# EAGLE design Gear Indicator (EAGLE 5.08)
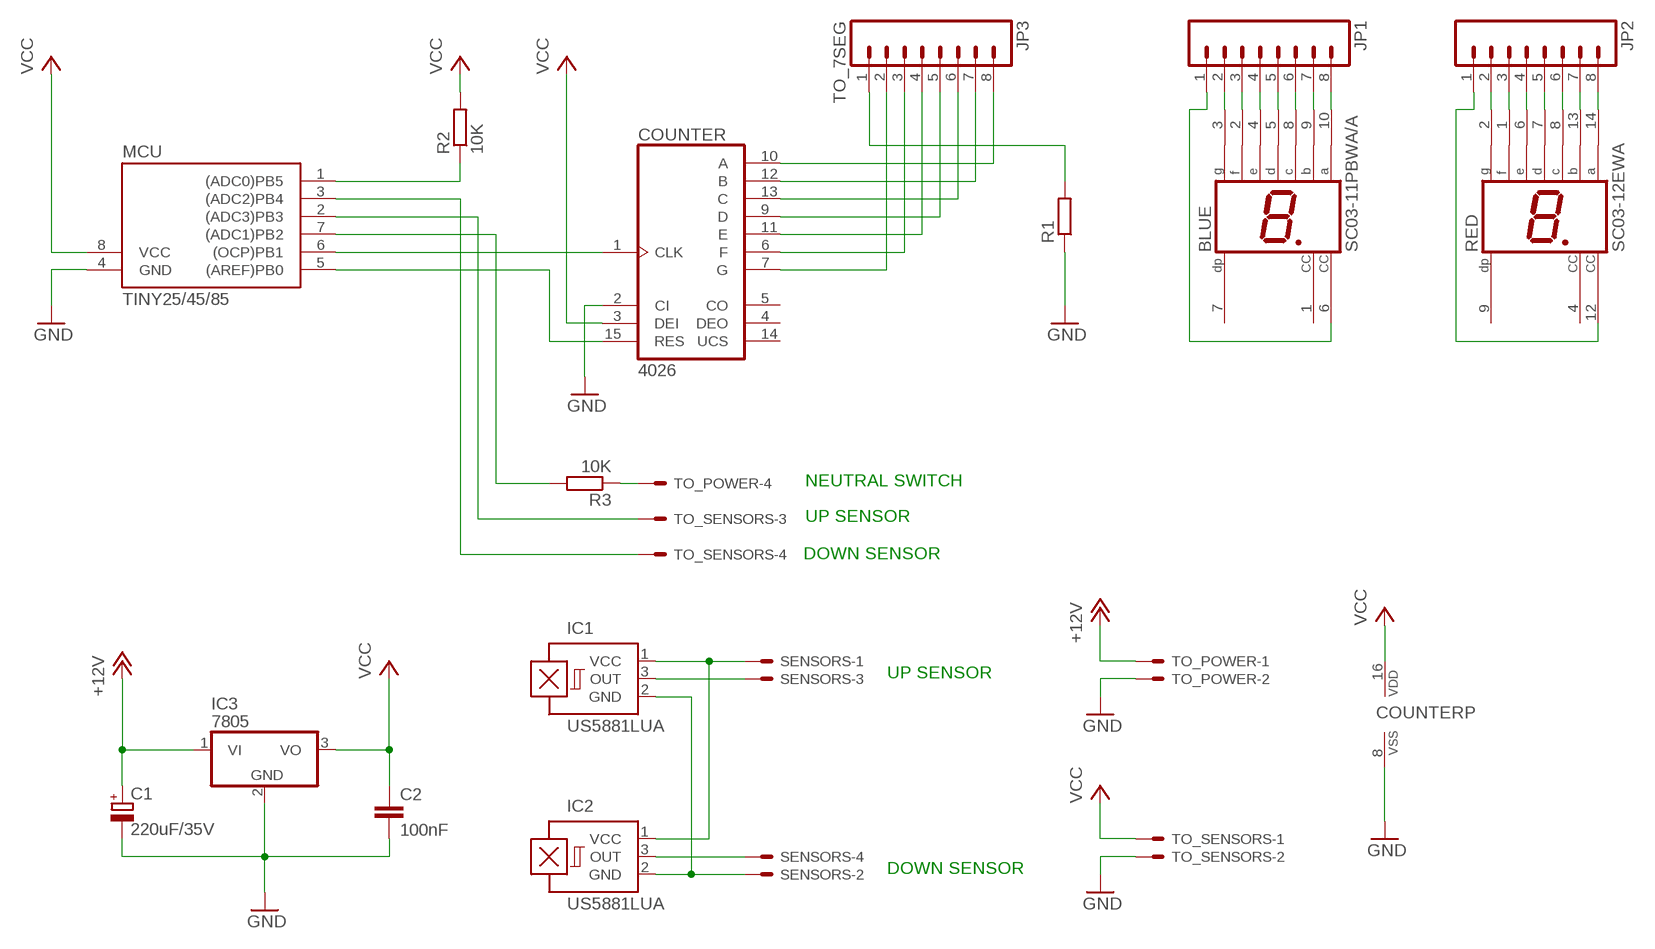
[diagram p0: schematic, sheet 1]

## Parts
BLUE  SC03-11PBWA/A  [0.3A]
C1  220uF/35V  CPOL-EUE2.5-6  [E2,5-6]
C2  100nF  C-EU050-030X075  [C050-030X075]
COUNTER  4026  4026TS  [TSSOP16]
IC1  US5881LUA  A1202UA  [SIP3-UA]
IC2  US5881LUA  A1202UA  [SIP3-UA]
IC3  7805  7805TV  [TO220V]
JP1  M08  [1X08]
JP2  M08  [1X08]
JP3  TO_7SEG  M08  [1X08]
MCU  TINY25/45/85  TINY25/45/85-20SU  [SOIC8]
R1  R-EU_0309/12  [0309/12]
R2  10K  R-EU_0207/10  [0207/10]
R3  10K  R-EU_0207/10  [0207/10]
RED  SC03-12EWA  [0.3B]
SENSORS  22-05-7048-04  [7395-04]
TO_POWER  22-05-7048-04  [7395-04]
TO_SENSORS  22-05-7048-04  [7395-04]

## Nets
+12V: C1.+ IC3.1(VI) TO_POWER.1
A: COUNTER.10(A) JP3.8
B: COUNTER.12(B) JP3.7
BLUE_A: BLUE.10(A) JP1.8
BLUE_B: BLUE.9(B) JP1.7
BLUE_C: BLUE.8(C) JP1.6
BLUE_CC: BLUE.6(CC) JP1.1
BLUE_D: BLUE.5(D) JP1.5
BLUE_E: BLUE.4(E) JP1.4
BLUE_F: BLUE.2(F) JP1.3
BLUE_G: BLUE.3(G) JP1.2
C: COUNTER.13(C) JP3.6
CC: JP3.1 R1.2
CLK: COUNTER.1(CLK) MCU.6((OCP)PB1)
D: COUNTER.9(D) JP3.5
DOWN: MCU.3((ADC2)PB4) TO_SENSORS.4
E: COUNTER.11(E) JP3.4
F: COUNTER.6(F) JP3.3
G: COUNTER.7(G) JP3.2
GND: C1.- C2.2 COUNTER.2(CI) COUNTER.8(VSS) IC3.2(GND) MCU.4(GND) R1.1 TO_POWER.2 TO_SENSORS.2
N$31: R3.1 TO_POWER.4
N$32: IC1.2(GND) IC2.2(GND) SENSORS.2
N$36: IC1.1(VCC) IC2.1(VCC) SENSORS.1
N$38: IC1.3(OUT) SENSORS.3
N$40: IC2.3(OUT) SENSORS.4
NEUTRAL: MCU.7((ADC1)PB2) R3.2
RED_A: JP2.8 RED.14(A)
RED_B: JP2.7 RED.13(B)
RED_C: JP2.6 RED.8(C)
RED_CC: JP2.1 RED.12(CC)
RED_D: JP2.5 RED.7(D)
RED_E: JP2.4 RED.6(E)
RED_F: JP2.3 RED.1(F)
RED_G: JP2.2 RED.2(G)
RESET: MCU.1((ADC0)PB5) R2.1
UP: MCU.2((ADC3)PB3) TO_SENSORS.3
VCC: C2.1 COUNTER.3(DEI) COUNTER.16(VDD) IC3.3(VO) MCU.8(VCC) R2.2 TO_SENSORS.1
ZERO: COUNTER.15(RES) MCU.5((AREF)PB0)
Unconnected: BLUE.1(CC) BLUE.7(DP) COUNTER.4(DEO) COUNTER.5(CO) COUNTER.14(UCS) RED.4(CC) RED.9(DP) TO_POWER.3

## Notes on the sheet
- NEUTRAL SWITCH
- UP SENSOR
- DOWN SENSOR
- UP SENSOR
- DOWN SENSOR

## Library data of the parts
BLUE = #vp-knightbright-0.3:SC03-11PBWA/A: LED DISPLAY 0.3'' 1-character 7-segment
C1 = rcl:CPOL-EU: POLARIZED CAPACITOR, European symbol
C2 = rcl:C-EU: CAPACITOR, European symbol
COUNTER = #vp-40xx:4026: Decade COUNTER/DIVIDER, 7-seg. outputs
IC1 IC2 = allegro:A12*?: Hall-effect bipolar switch Source: http://www.allegromicro.com/en/Products/Part_Numbers/1202/1202.pdf
IC3 = linear:78*: Positive VOLTAGE REGULATOR Source: http://cache.national.com/ds/LM/LM78L05.pdf http://www.fairchildsemi.com/ds/LM/LM7805.pdf
JP1-JP3 = SparkFun:M08: Header 8 Standard 8-pin 0.1" header. Use with straight break away headers (SKU : PRT-00116), right angle break away headers (PRT-00553), swiss pins (PRT-00743), machine pins (PRT-00117), and female headers (PRT-00115).
MCU = #vp-avr-6:TINY25/45/85
R1-R3 = rcl:R-EU_: RESISTOR, European symbol
RED = #vp-knightbright-0.3:SC03-12EWA: LED DISPLAY 0.3'' 1-character 7-segment
SENSORS TO_POWER TO_SENSORS = con-molex:22-?-04: CONNECTOR wire to board 2.54 mm (.1 inch) pitch header

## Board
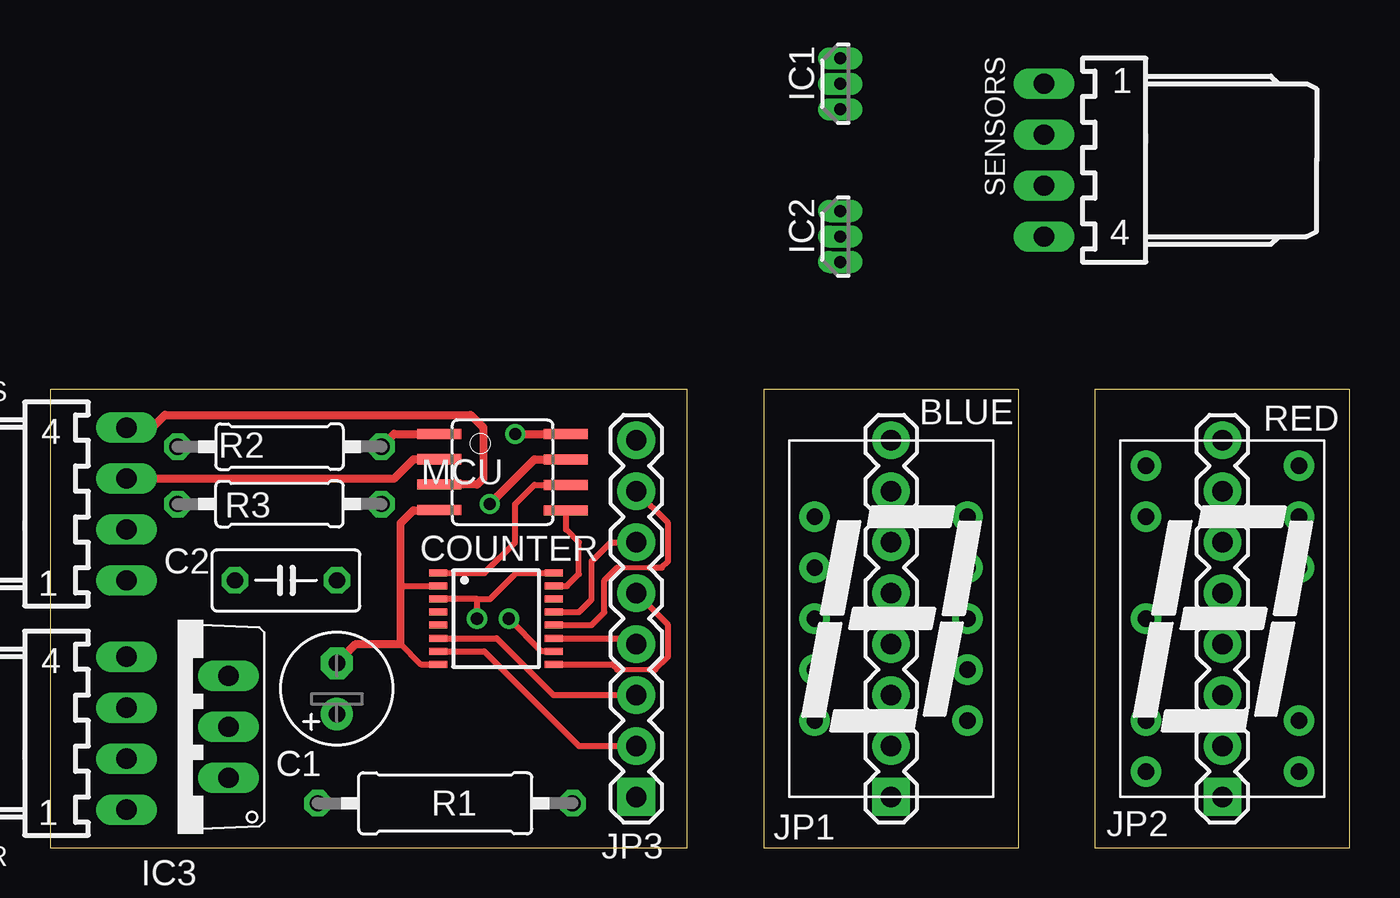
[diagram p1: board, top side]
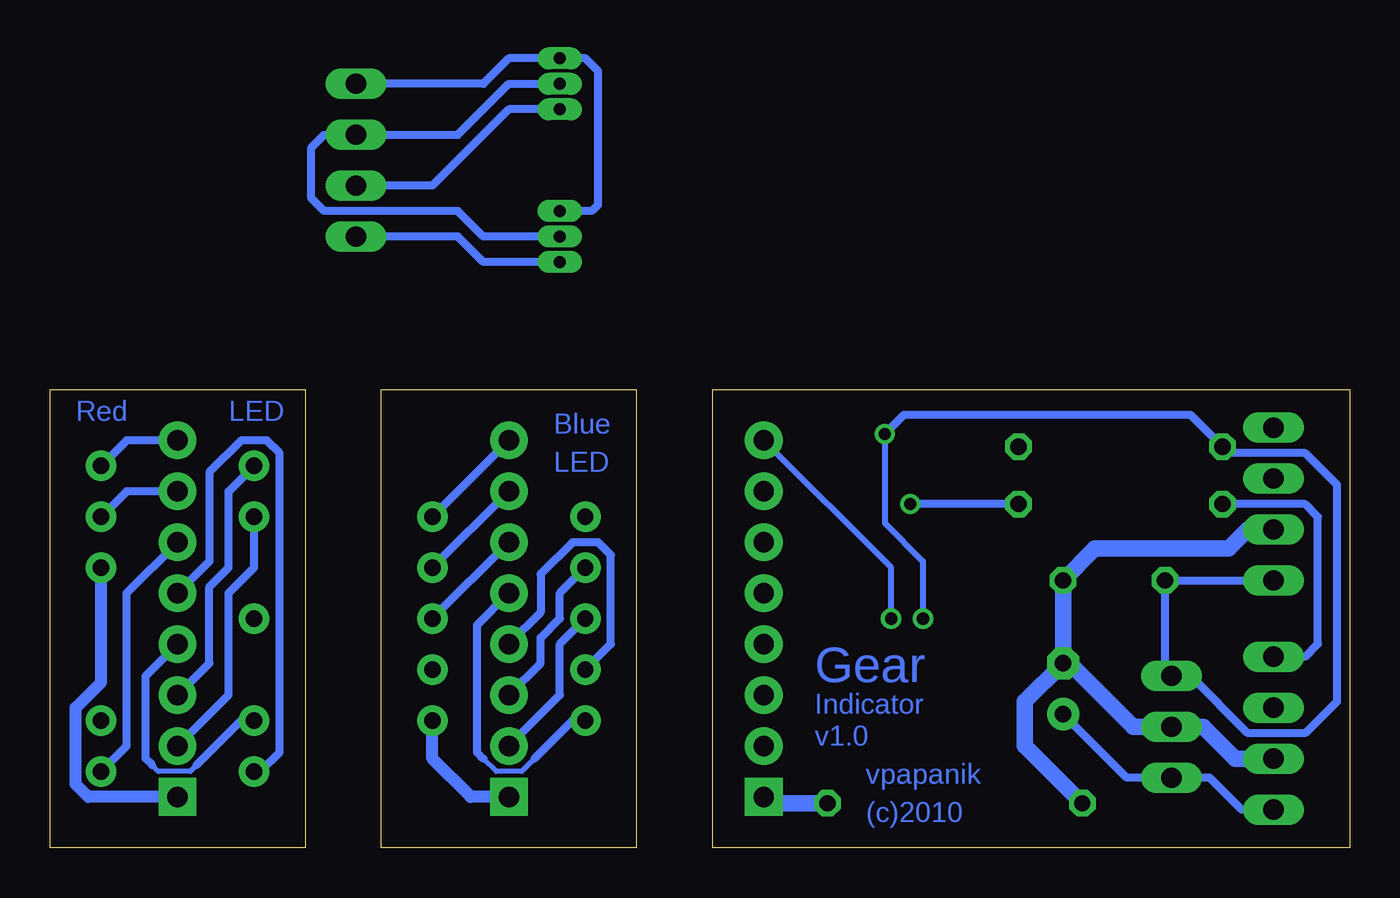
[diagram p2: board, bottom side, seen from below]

Size 64.77 x 22.86 mm. Coordinates in mm from the lower left corner, seen from the top.
Outline: 0,0 31.75,0 31.75,22.86 0,22.86 0,0
Outline: 48.26,22.86 35.56,22.86 35.56,0 48.26,0 48.26,22.86
Outline: 64.77,0 64.77,22.86 52.07,22.86 52.07,0 64.77,0
Copper layers (1*16): Top 0.035mm / dielectric 1.5mm / Bottom 0.035mm
Design rules "default *": minimum track width 10mil, minimum drill 24mil, track to track 8mil, track to pad 8mil, pad to pad 8mil, via to via 8mil, smd to smd 8mil, copper to edge 32mil, drill to drill 8mil, minimum pad ring 10mil, minimum via ring 8mil, stop-mask expansion 4mil, vias tented up to drill 0mil, thermal gap 10mil

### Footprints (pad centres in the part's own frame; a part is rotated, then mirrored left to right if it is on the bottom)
0.3A = drill 0.813 pad 1.524 round: 1 -3.81,5.08; 2 -3.81,2.54; 3 -3.81,0; 4 -3.81,-2.54; 5 -3.81,-5.08; 6 3.81,-5.08; 7 3.81,-2.54; 8 3.81,0; 9 3.81,2.54; 10 3.81,5.08
E2,5-6 = drill 0.813 pad 1.6 round: + -1.27,0 | drill 0.813 pad 1.6 octagon: - 1.27,0
C050-030X075 = drill 0.813 octagon: 1 -2.54,0; 2 2.54,0
TSSOP16 = smd 0.9 x 0.35: 1 -2.875,2.275; 2 -2.875,1.625; 3 -2.875,0.975; 4 -2.875,0.325; 5 -2.875,-0.325; 6 -2.875,-0.975; 7 -2.875,-1.625; 8 -2.875,-2.275; 9 2.875,-2.275; 10 2.875,-1.625; 11 2.875,-0.975; 12 2.875,-0.325; 13 2.875,0.325; 14 2.875,0.975; 15 2.875,1.625; 16 2.875,2.275
SIP3-UA = drill 0.6 pad 0.7 long: 1 -1.27,0; 2 0,0; 3 1.27,0
TO220V = drill 1.016 long: 1 -2.54,-2.54; 2 0,-2.54; 3 2.54,-2.54
1X08 = drill 1.016 pad 1.88 square: 1 0,0 | drill 1.016 pad 1.88 round: 2 2.54,0; 3 5.08,0; 4 7.62,0; 5 10.16,0; 6 12.7,0; 7 15.24,0; 8 17.78,0
SOIC8 = smd 0.5 x 2.2: 1 -1.905,-3.154; 2 -0.645,-3.154; 3 0.625,-3.154; 4 1.895,-3.154; 5 1.905,3.154; 6 0.635,3.154; 7 -0.635,3.154; 8 -1.905,3.154
0309/12 = drill 0.813 octagon: 1 -6.35,0; 2 6.35,0
0207/10 = drill 0.813 octagon: 1 -5.08,0; 2 5.08,0
0.3B = drill 0.813 pad 1.524 round: 1 -3.81,7.62; 2 -3.81,5.08; 4 -3.81,0; 6 -3.81,-5.08; 7 -3.81,-7.62; 8 3.81,-7.62; 9 3.81,-5.08; 12 3.81,2.54; 13 3.81,5.08; 14 3.81,7.62
7395-04 = drill 1.016 long: 1 3.81,0; 2 1.27,0; 3 -1.27,0; 4 -3.81,0

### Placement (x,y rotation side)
BLUE  41.91,11.43 0 top
C1  14.29,7.94 90 top
C2  11.75,13.33 0 top
COUNTER  22.23,11.43 0 top
IC1  39.37,38.1 270 top  (outside the outline)
IC2  39.37,30.48 270 top  (outside the outline)
IC3  6.35,6.03 90 top
JP1  41.91,2.54 90 top
JP2  58.42,2.54 90 top
JP3  29.21,2.54 90 top
MCU  22.54,18.73 270 top
R1  19.68,2.22 0 top
R2  11.43,20 180 top
R3  11.43,17.15 0 top
RED  58.42,11.43 0 top
SENSORS  49.53,34.29 90 top  (outside the outline)
TO_POWER  3.81,5.71 270 top
TO_SENSORS  3.81,17.15 270 top

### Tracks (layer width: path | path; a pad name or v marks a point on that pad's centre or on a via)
+12V
  Bottom 0.406: TO_POWER.1 5.4,1.91 6.98,3.49 IC3.1 11.11,3.49 C1.+
A  (via drill 0.61 pad 0.61)
  Top 0.305: COUNTER.10 24.48,9.8 v22.86,11.43
  Bottom 0.305: v22.86,11.43 22.86,13.97 JP3.8
B
  Top 0.254: 28.58,13.97 29.84,13.97
  Top 0.305: JP3.7 30.8,16.19 30.8,14.29 30.48,13.97 29.84,13.97 | COUNTER.12 26.99,11.11 27.62,11.75 27.62,13.33 28.26,13.97 28.58,13.97
BLUE_A
  Bottom 0.406: BLUE.10 JP1.8
BLUE_B
  Bottom 0.406: BLUE.9 JP1.7
BLUE_C
  Bottom 0.406: BLUE.8 JP1.6
BLUE_CC
  Bottom 0.61: JP1.1 43.81,2.54 45.72,4.45 BLUE.6
BLUE_D
  Bottom 0.254: 40.64,4.45 41.27,3.81 42.55,3.81 43.18,4.45
  Bottom 0.406: JP1.5 43.5,11.11 43.5,4.76 43.18,4.45 | BLUE.5 38.73,6.35 40.64,4.45
BLUE_E
  Bottom 0.406: JP1.4 40.32,11.75 40.32,13.65 38.73,15.24 37.47,15.24 36.83,14.6 36.83,10.16 BLUE.4
BLUE_F
  Bottom 0.406: BLUE.2 39.37,12.7 39.37,11.43 40.32,10.48 40.32,9.21 JP1.3
BLUE_G
  Bottom 0.406: JP1.2 39.37,7.62 39.37,10.16 BLUE.3
C
  Top 0.305: COUNTER.13 26.36,11.76 26.99,12.38 26.99,14.29 27.94,15.24 JP3.6
CC
  Bottom 0.813: R1.2 28.89,2.22 JP3.1
CLK
  Top 0.305: MCU.6 24.13,18.1 23.18,17.15 23.18,15.24 21.64,13.71 COUNTER.1
D
  Top 0.254: 28.58,8.89 29.84,8.89
  Top 0.305: COUNTER.9 27.99,9.15 28.26,8.89 28.58,8.89 | JP3.5 30.8,11.11 30.8,9.53 30.16,8.89 29.84,8.89
DOWN
  Top 0.406: MCU.3 21.28,18.11 21.59,18.41 21.59,20.95 20.95,21.59 5.71,21.59 5.08,20.95 TO_SENSORS.4
E
  Top 0.305: COUNTER.11 28.91,10.46 JP3.4
F
  Top 0.305: COUNTER.6 22.25,10.46 25.08,7.62 JP3.3
G
  Top 0.305: COUNTER.7 21.63,9.8 26.35,5.08 JP3.2
GND
  Top 0.305: 19.38,16.83 MCU.4 | COUNTER.2 17.5,13.06 17.46,13.02 | COUNTER.8 18.47,9.15 17.46,10.16
  Top 0.406: 19.38,16.83 18.1,16.83 17.46,16.19 17.46,13.02 17.46,10.16 15.24,10.16 C1.-
  Bottom 0.813: TO_POWER.2 5.71,4.45 7.3,6.03 IC3.2 10.8,6.03 13.97,9.21 C1.- | C1.- C2.2 12.7,14.92 6.03,14.92 5.08,15.87 TO_SENSORS.2 | R1.1 16.19,5.08 16.19,7.3 C1.-
N$31
  Bottom 0.406: R3.1 2.22,17.15 1.59,16.51 1.59,10.16 2.22,9.53 TO_POWER.4
N$32
  Bottom 0.406: IC1.2 41.91,38.1 44.45,35.56 SENSORS.2 51.12,35.56 51.75,34.93 51.75,32.39 51.12,31.75 44.45,31.75 43.18,30.48 IC2.2
N$36
  Bottom 0.406: SENSORS.1 43.18,38.1 41.91,39.37 IC1.1 38.1,39.37 37.47,38.73 37.47,32.07 37.78,31.75 IC2.1
N$38
  Bottom 0.406: SENSORS.3 45.72,33.02 41.91,36.83 IC1.3
N$40
  Bottom 0.406: SENSORS.4 44.45,30.48 43.18,29.21 IC2.3
NEUTRAL  (via drill 0.61 pad 1.02)
  Top 0.406: MCU.7 24.13,19.37 v21.91,17.15
  Bottom 0.406: R3.2 v21.91,17.15
RED_A
  Bottom 0.406: JP2.8 60.96,20.32 RED.14
RED_B
  Bottom 0.406: JP2.7 60.96,17.78 RED.13
RED_C
  Bottom 0.406: RED.8 60.96,5.08 60.96,12.7 JP2.6
RED_CC
  Bottom 0.61: RED.12 62.23,8.26 63.5,6.98 63.5,3.18 62.87,2.54 JP2.1
RED_D
  Bottom 0.406: RED.7 54.29,3.81 53.34,4.76 53.34,19.69 53.98,20.32 55.24,20.32 56.83,18.73 56.83,14.29 JP2.5
RED_E
  Bottom 0.254: 57.47,4.13 57.79,3.81 59.37,3.81 59.69,4.13
  Bottom 0.406: JP2.4 60.01,8.57 60.01,4.45 59.69,4.13 | RED.6 55.24,6.35 57.47,4.13
RED_F
  Bottom 0.406: JP2.3 56.83,9.21 56.83,13.02 55.88,13.97 55.88,17.78 RED.1
RED_G
  Bottom 0.406: JP2.2 55.88,7.62 55.88,12.7 54.61,13.97 RED.2
RESET
  Top 0.406: R2.1 17.14,20.64 MCU.1
UP
  Top 0.406: MCU.2 18.11,19.38 17.14,18.41 TO_SENSORS.3
VCC  (via drill 0.61 pad 0.61, 0.61 pad 1.02)
  Top 0.305: COUNTER.16 23.23,13.71 21.93,12.4 21.27,12.4 | 21.27,12.4 COUNTER.3 | v21.27,11.43 21.27,12.4
  Top 0.406: v23.18,20.64 MCU.8
  Bottom 0.305: v23.18,20.64 23.18,16.19 21.27,14.29 v21.27,11.43
  Bottom 0.406: TO_SENSORS.1 C2.1 9.21,8.89 IC3.3 7.94,8.57 5.08,5.71 2.22,5.71 0.63,7.3 0.63,18.1 2.22,19.69 6.03,19.69 R2.2 7.94,21.59 22.23,21.59 v23.18,20.64
ZERO
  Top 0.305: COUNTER.15 25.76,13.06 26.35,13.65 26.35,15.24 25.72,15.87 25.72,16.81 MCU.5

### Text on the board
Bottom: Blue | LED | Red | LED | Gear | Indicator | v1.0 | vpapanik | (c)2010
